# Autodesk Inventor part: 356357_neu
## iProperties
Created: 2006-10
Part Number: 356357_neu
Material: 1.0718.07
Description: Bolzen
Document SubType Name: Modeling
Designer: OSchmidt
Density: 7.84 g/cm^3
Mass: 35.0794 g
Surface Area: 17.2237 cm^2
Volume: 4.47441 cm^3
Abmessung: Rd. 18
HalbzeugNorm: DIN 671
Zweck: 266454
Author: OSchmidt
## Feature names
1. Extrusion2
2. Fase1 [Chamfer]
3. Extrusion4
